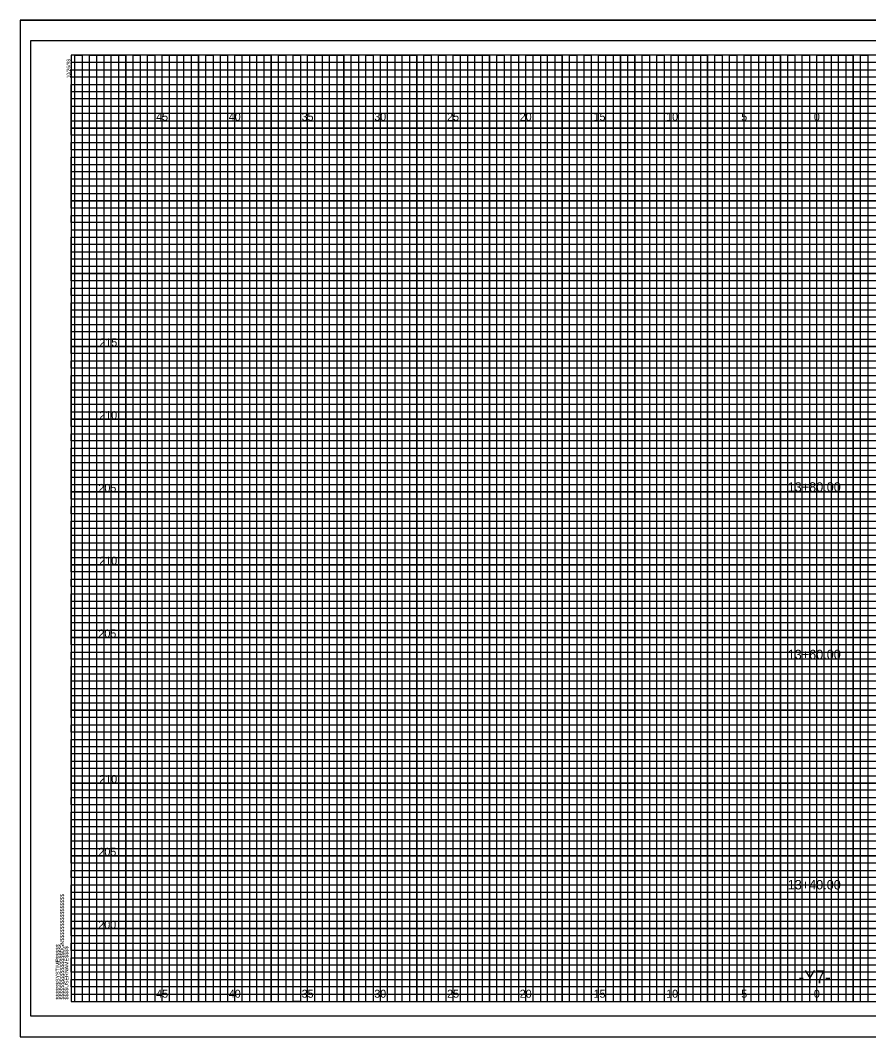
# Model space of a CAD drawing. Extents: x -4 to 103, y -2 to 351.
# Drawn here: x -3.5 to 54.8, y 280.9 to 350.7 of the extents above; entities that cross this region are included whole.
import ezdxf

# ---------------------------------------------------------------- set-up
doc = ezdxf.new("R2010")
doc.units = 0
for name, color, linetype in [('Exist XS Ground Line', 7, 'Continuous'), ('Old_Level_10', 7, 'Continuous'), ('Old_Level_16', 7, 'Continuous'), ('Old_Level_3', 7, 'Continuous'), ('Old_Level_4', 7, 'Continuous'), ('Old_Level_5', 7, 'Continuous'), ('Old_Level_6', 7, 'Continuous'), ('Old_Level_8', 7, 'Continuous'), ('Prop XS Finish Grade', 7, 'Continuous'), ('Prop XS SE Text', 7, 'Continuous'), ('Prop XS Subgrade Earthwork', 7, 'Continuous')]:
    doc.layers.add(name, color=color, linetype=linetype)

msp = doc.modelspace()

# ---------------------------------------------------------------- linework, layer by layer
at = {"layer": 'Old_Level_10'}
for p, q in [((1.25, 283.3), (1.25, 348.3)), ((3.75, 283.3), (3.75, 348.3)), ((6.25, 283.3), (6.25, 348.3)), ((8.75, 283.3), (8.75, 348.3)), ((11.25, 283.3), (11.25, 348.3)), ((13.75, 283.3), (13.75, 348.3)), ((16.25, 283.3), (16.25, 348.3)), ((18.75, 283.3), (18.75, 348.3)), ((21.25, 283.3), (21.25, 348.3)), ((23.75, 283.3), (23.75, 348.3)), ((26.25, 283.3), (26.25, 348.3)), ((28.75, 283.3), (28.75, 348.3)), ((31.25, 283.3), (31.25, 348.3)), ((33.75, 283.3), (33.75, 348.3)), ((36.25, 283.3), (36.25, 348.3)), ((38.75, 283.3), (38.75, 348.3)), ((41.25, 283.3), (41.25, 348.3)), ((43.75, 283.3), (43.75, 348.3)), ((46.25, 283.3), (46.25, 348.3)), ((48.75, 283.3), (48.75, 348.3)), ((51.25, 283.3), (51.25, 348.3)), ((53.75, 283.3), (53.75, 348.3)), ((0, 345.8), (74.25, 345.8)), ((0, 343.3), (102.5, 343.3)), ((0, 340.8), (102.5, 340.8)), ((0, 338.3), (102.5, 338.3)), ((0, 335.8), (102.5, 335.8)), ((0, 333.3), (102.5, 333.3)), ((0, 330.8), (102.5, 330.8)), ((0, 328.3), (102.5, 328.3)), ((0, 325.8), (102.5, 325.8)), ((0, 323.3), (102.5, 323.3)), ((0, 320.8), (102.5, 320.8)), ((0, 318.3), (102.5, 318.3)), ((0, 315.8), (102.5, 315.8)), ((0, 313.3), (102.5, 313.3)), ((0, 310.8), (102.5, 310.8)), ((0, 308.3), (102.5, 308.3)), ((0, 305.8), (102.5, 305.8)), ((0, 303.3), (102.5, 303.3)), ((0, 300.8), (102.5, 300.8)), ((0, 298.3), (102.5, 298.3)), ((0, 295.8), (102.5, 295.8)), ((0, 293.3), (102.5, 293.3)), ((0, 290.8), (102.5, 290.8)), ((0, 288.3), (102.5, 288.3)), ((0, 285.8), (102.5, 285.8))]:
    msp.add_line(p, q, dxfattribs=at)
at = {"layer": 'Old_Level_3'}
for p, q in [((-3.5, 350.7), (103.4, 350.7)), ((-3.5, 350.7), (-3.5, 280.875)), ((-3.5, 280.875), (102.1625, 280.875))]:
    msp.add_line(p, q, dxfattribs=at)
at = {"layer": 'Old_Level_4'}
for points in [[(0, 345.3), (0, 346.3), (74.25, 346.3), (74.25, 346.8), (0, 346.8), (0, 347.3), (74.25, 347.3), (74.25, 347.8), (0, 347.8)], [(0.25, 283.3), (0.25, 348.3), (0.75, 348.3), (0.75, 283.3), (1.75, 283.3), (1.75, 348.3), (2.25, 348.3), (2.25, 283.3), (2.75, 283.3), (2.75, 348.3), (3.25, 348.3), (3.25, 283.3), (4.25, 283.3), (4.25, 348.3), (4.75, 348.3), (4.75, 283.3), (5.25, 283.3), (5.25, 348.3), (5.75, 348.3), (5.75, 283.3), (6.75, 283.3), (6.75, 348.3), (7.25, 348.3), (7.25, 283.3), (7.75, 283.3), (7.75, 348.3), (8.25, 348.3), (8.25, 283.3), (9.25, 283.3), (9.25, 348.3), (9.75, 348.3), (9.75, 283.3), (10.25, 283.3), (10.25, 348.3), (10.75, 348.3), (10.75, 283.3), (11.75, 283.3), (11.75, 348.3), (12.25, 348.3), (12.25, 283.3), (12.75, 283.3), (12.75, 348.3), (13.25, 348.3), (13.25, 283.3), (14.25, 283.3), (14.25, 348.3), (14.75, 348.3), (14.75, 283.3), (15.75, 283.3), (15.25, 283.3), (15.25, 348.3), (15.75, 348.3), (15.75, 283.3), (16.75, 283.3), (16.75, 348.3), (17.25, 348.3), (17.25, 283.3), (17.75, 283.3), (17.75, 348.3), (18.25, 348.3), (18.25, 283.3), (19.25, 283.3), (19.25, 348.3), (19.75, 348.3), (19.75, 283.3), (20.25, 283.3), (20.25, 348.3), (20.75, 348.3), (20.75, 283.3), (21.75, 283.3), (21.75, 348.3), (22.25, 348.3), (22.25, 283.3), (22.75, 283.3), (22.75, 348.3), (23.25, 348.3), (23.25, 283.3), (24.25, 283.3), (24.25, 348.3), (24.75, 348.3), (24.75, 283.3), (25.25, 283.3), (25.25, 348.3), (25.75, 348.3), (25.75, 283.3), (26.75, 283.3), (26.75, 348.3), (27.25, 348.3), (27.25, 283.3), (27.75, 283.3), (27.75, 348.3), (28.25, 348.3), (28.25, 283.3), (29.25, 283.3), (29.25, 348.3), (29.75, 348.3), (29.75, 283.3), (30.25, 283.3), (30.25, 348.3), (30.75, 348.3), (30.75, 283.3)], [(30.75, 283.3), (31.75, 283.3), (31.75, 348.3), (32.25, 348.3), (32.25, 283.3), (32.75, 283.3), (32.75, 348.3), (33.25, 348.3), (33.25, 283.3), (34.25, 283.3), (34.25, 348.3), (34.75, 348.3), (34.75, 283.3), (35.25, 283.3), (35.25, 348.3), (35.75, 348.3), (35.75, 283.3), (36.75, 283.3), (36.75, 348.3), (37.25, 348.3), (37.25, 283.3), (37.75, 283.3), (37.75, 348.3), (37.75, 283.3)], [(38.25, 348.3), (38.25, 283.3), (39.25, 283.3), (39.25, 348.3), (39.75, 348.3), (39.75, 283.3), (40.25, 283.3), (40.25, 348.3), (40.75, 348.3), (40.75, 283.3), (41.75, 283.3), (41.75, 348.3), (42.25, 348.3), (42.25, 283.3), (42.75, 283.3), (42.75, 348.3), (43.25, 348.3), (43.25, 283.3), (43.75, 283.3), (44.25, 283.3), (44.25, 348.3), (44.75, 348.3), (44.75, 283.3), (45.25, 283.3), (45.25, 348.3), (45.75, 348.3), (45.75, 283.3), (46.75, 283.3), (46.75, 348.3), (47.25, 348.3), (47.25, 283.3), (47.75, 283.3), (47.75, 348.3), (48.25, 348.3), (48.25, 283.3), (49.25, 283.3), (49.25, 348.3), (49.75, 348.3), (49.75, 283.3), (50.25, 283.3), (50.25, 348.3), (50.75, 348.3), (50.75, 283.3), (51.75, 283.3), (51.75, 348.3), (52.25, 348.3), (52.25, 283.3), (52.75, 283.3), (52.75, 348.3), (53.25, 348.3), (53.25, 283.3), (54.25, 283.3), (54.25, 348.3), (54.75, 348.3), (54.75, 283.3), (55.25, 283.3)], [(102.5, 345.3), (0, 345.3)], [(102.5, 344.3), (0, 344.3), (0, 344.8), (102.5, 344.8)], [(102.5, 342.8), (0, 342.8), (0, 343.8), (102.5, 343.8)], [(102.5, 341.8), (0, 341.8), (0, 342.3), (102.5, 342.3)], [(102.5, 340.3), (0, 340.3), (0, 341.3), (102.5, 341.3)], [(102.5, 339.3), (0, 339.3), (0, 339.8), (102.5, 339.8)], [(102.5, 337.8), (0, 337.8), (0, 338.8), (102.5, 338.8)], [(102.5, 336.8), (0, 336.8), (0, 337.3), (102.5, 337.3)], [(0, 336.3), (102.5, 336.3)], [(102.5, 335.3), (0, 335.3)], [(102.5, 334.3), (0, 334.3), (0, 334.8), (102.5, 334.8)], [(102.5, 332.8), (0, 332.8), (0, 333.8), (102.5, 333.8)], [(102.5, 331.8), (0, 331.8), (0, 332.3), (102.5, 332.3)], [(102.5, 330.3), (0, 330.3), (0, 331.3), (102.5, 331.3)], [(102.5, 329.3), (0, 329.3), (0, 329.8), (102.5, 329.8)], [(102.5, 327.8), (0, 327.8), (0, 328.8), (102.5, 328.8)], [(102.5, 326.8), (0, 326.8), (0, 327.3), (102.5, 327.3)], [(102.5, 325.3), (0, 325.3), (0, 326.3), (102.5, 326.3)], [(102.5, 324.3), (0, 324.3), (0, 324.8), (102.5, 324.8)], [(102.5, 322.8), (0, 322.8), (0, 323.8), (102.5, 323.8)], [(102.5, 321.8), (0, 321.8), (0, 322.3), (102.5, 322.3)], [(102.5, 320.3), (0, 320.3), (0, 321.3), (102.5, 321.3)], [(102.5, 319.3), (0, 319.3), (0, 319.8), (102.5, 319.8)], [(102.5, 317.8), (0, 317.8), (0, 318.8), (102.5, 318.8)], [(102.5, 316.8), (0, 316.8), (0, 317.3), (102.5, 317.3)], [(102.5, 315.3), (0, 315.3), (0, 316.3), (102.5, 316.3)], [(102.5, 314.3), (0, 314.3), (0, 314.8)], [(0, 314.8), (102.5, 314.8)], [(102.5, 312.8), (0, 312.8), (0, 313.8), (102.5, 313.8)], [(102.5, 311.8), (0, 311.8), (0, 312.3), (102.5, 312.3)], [(102.5, 310.3), (0, 310.3), (0, 311.3), (102.5, 311.3)], [(102.5, 309.3), (0, 309.3), (0, 309.8), (102.5, 309.8)], [(102.5, 307.8), (0, 307.8), (0, 308.8), (102.5, 308.8)], [(102.5, 306.8), (0, 306.8), (0, 307.3), (102.5, 307.3)], [(102.5, 305.3), (0, 305.3), (0, 306.3), (102.5, 306.3)], [(102.5, 304.3), (0, 304.3), (0, 304.8), (102.5, 304.8)], [(102.5, 302.8), (0, 302.8), (0, 303.8), (102.5, 303.8)], [(102.5, 301.8), (0, 301.8), (0, 302.3), (102.5, 302.3)], [(102.5, 300.3), (0, 300.3), (0, 301.3), (102.5, 301.3)], [(102.5, 299.3), (0, 299.3), (0, 299.8), (102.5, 299.8)], [(102.5, 297.8), (0, 297.8), (0, 298.8), (102.5, 298.8)], [(102.5, 296.8), (0, 296.8), (0, 297.3), (102.5, 297.3)], [(102.5, 295.3), (0, 295.3), (0, 296.3), (102.5, 296.3)], [(102.5, 294.3), (0, 294.3), (0, 294.8), (102.5, 294.8)], [(102.5, 292.8), (0, 292.8), (0, 293.8), (102.5, 293.8)], [(102.5, 291.8), (0, 291.8), (0, 292.3), (102.5, 292.3)], [(102.5, 290.3), (0, 290.3), (0, 291.3), (102.5, 291.3)], [(102.5, 289.3), (0, 289.3), (0, 289.8), (102.5, 289.8)], [(102.5, 287.8), (0, 287.8), (0, 288.8), (102.5, 288.8)], [(102.5, 286.8), (0, 286.8), (0, 287.3), (102.5, 287.3)], [(102.5, 285.3), (0, 285.3), (0, 286.3), (102.5, 286.3)], [(102.5, 284.3), (0, 284.3), (0, 284.8), (102.5, 284.8)], [(0, 283.8), (102.5, 283.8)]]:
    msp.add_lwpolyline(points, dxfattribs=at)
at = {"layer": 'Old_Level_5'}
msp.add_lwpolyline([(103.4, 350.7), (-3.5, 350.7), (-3.5, 280.875), (103.4, 280.875)], close=True, dxfattribs=at)
at = {"layer": 'Old_Level_6'}
for p, q in [((0, 283.3), (0, 283.3)), ((0, 283.3), (0, 283.3)), ((-3.5, 280.875), (103.4, 280.875))]:
    msp.add_line(p, q, dxfattribs=at)
msp.add_lwpolyline([(102.5, 348.3), (0, 348.3), (0, 283.3), (102.5, 283.3)], close=True, dxfattribs=at)
at = {"layer": 'Old_Level_8'}
for points in [[(1.25, 283.3), (1.25, 348.3), (3.75, 348.3), (3.75, 283.3), (6.25, 283.3), (6.25, 348.3), (8.75, 348.3), (8.75, 283.3), (11.25, 283.3), (11.25, 348.3), (13.75, 348.3), (13.75, 283.3), (16.25, 283.3), (16.25, 348.3), (18.75, 348.3), (18.75, 283.3), (21.25, 283.3), (21.25, 348.3), (23.75, 348.3), (23.75, 283.3), (26.25, 283.3), (26.25, 348.3), (28.75, 348.3), (28.75, 283.3), (31.25, 283.3), (31.25, 348.3), (33.75, 348.3), (33.75, 283.3), (36.25, 283.3), (36.25, 348.3), (38.75, 348.3), (38.75, 283.3), (41.25, 283.3), (41.25, 348.3), (43.75, 348.3), (43.75, 283.3), (46.25, 283.3), (46.25, 348.3), (48.75, 348.3), (48.75, 283.3), (51.25, 283.3), (51.25, 348.3), (53.75, 348.3), (53.75, 283.3)], [(102.5, 343.3), (0, 343.3), (0, 345.8), (74.25, 345.8)], [(102.5, 338.3), (0, 338.3), (0, 340.8), (102.5, 340.8)], [(102.5, 333.3), (0, 333.3), (0, 335.8), (102.5, 335.8)], [(102.5, 328.3), (0, 328.3), (0, 330.8), (102.5, 330.8)], [(102.5, 323.3), (0, 323.3), (0, 325.8), (102.5, 325.8)], [(102.5, 318.3), (0, 318.3), (0, 320.8), (102.5, 320.8)], [(102.5, 313.3), (0, 313.3), (0, 315.8), (102.5, 315.8)], [(102.5, 308.3), (0, 308.3), (0, 310.8), (102.5, 310.8)], [(102.5, 303.3), (0, 303.3), (0, 305.8), (102.5, 305.8)], [(102.5, 298.3), (0, 298.3), (0, 300.8), (102.5, 300.8)], [(102.5, 293.3), (0, 293.3), (0, 295.8), (102.5, 295.8)], [(102.5, 288.3), (0, 288.3), (0, 290.8), (102.5, 290.8)], [(0, 285.8), (102.5, 285.8)]]:
    msp.add_lwpolyline(points, dxfattribs=at)
at = {"layer": 'Prop XS SE Text'}
msp.add_lwpolyline([(103, 349.3), (-2.8, 349.3), (-2.8, 282.3), (103, 282.3)], close=True, dxfattribs=at)

# ---------------------------------------------------------------- texts
at = {"layer": 'Exist XS Ground Line'}
msp.add_text('-Y7-', height=0.875, dxfattribs=at).set_placement((49.9985, 284.55))
at = {"layer": 'Old_Level_16'}
for s, p in [('45', (5.8399, 343.8)), ('40', (10.8313, 343.8)), ('35', (15.8399, 343.8)), ('30', (20.8313, 343.8)), ('25', (25.8399, 343.8)), ('20', (30.8313, 343.8)), ('15', (35.9058, 343.8)), ('10', (40.8971, 343.8)), ('5', (46.0574, 343.8)), ('0', (51.0488, 343.8)), ('0', (51.0488, 343.8)), ('45', (5.8399, 283.55)), ('40', (10.8313, 283.55)), ('35', (15.8399, 283.55)), ('30', (20.8313, 283.55)), ('25', (25.8399, 283.55)), ('20', (30.8313, 283.55)), ('15', (35.9058, 283.55)), ('10', (40.8971, 283.55)), ('5', (46.0574, 283.55)), ('0', (51.0488, 283.55)), ('0', (51.0488, 283.55))]:
    msp.add_text(s, height=0.55, dxfattribs=at).set_placement(p)
at = {"layer": 'Old_Level_6'}
for s, height, p in [('10/26/98', 0.25, (-0.0625, 346.7095)), ('$$$$$$$$$$$$$$$$DGN$$$$$$$$$$$$$$$$', 0.2625, (-0.5, 283.425)), ('$$$$$$SYSTIME$$$$$', 0.2625, (-0.7973, 283.4247)), ('$$$$USERNAME$$$$', 0.2625, (-0.2, 283.425))]:
    msp.add_text(s, height=height, rotation=90, dxfattribs=at).set_placement(p)
at = {"layer": 'Old_Level_8'}
msp.add_text('040397', height=0.0025, rotation=90, dxfattribs=at).set_placement((-0.0007, 348.2864))
at = {"layer": 'Prop XS Finish Grade'}
for s, p in [('215', (1.9383, 328.3)), ('210', (1.9296, 323.3)), ('205', (1.8724, 318.3)), ('210', (1.9296, 313.3)), ('205', (1.8724, 308.3)), ('210', (1.9296, 298.3)), ('205', (1.8724, 293.3)), ('200', (1.8638, 288.3))]:
    msp.add_text(s, height=0.55, dxfattribs=at).set_placement(p)
at = {"layer": 'Prop XS Subgrade Earthwork'}
for s, p in [('13+80.00', (49.2508, 318.3135)), ('13+60.00', (49.2508, 306.8067)), ('13+40.00', (49.2508, 290.9904))]:
    msp.add_text(s, height=0.65, dxfattribs=at).set_placement(p)

doc.saveas('drawing.dxf')
